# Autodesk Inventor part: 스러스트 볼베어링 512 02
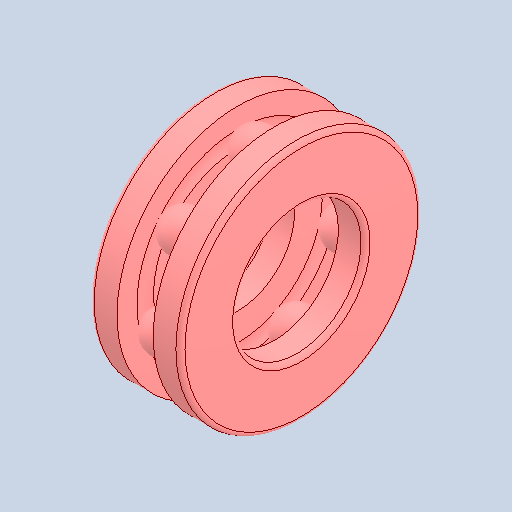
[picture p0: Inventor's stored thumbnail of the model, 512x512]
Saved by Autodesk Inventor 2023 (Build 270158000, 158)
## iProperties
Created: 2024-09
Part Number: 스러스트 볼베어링 512 02
Material: 강철, 연강
Description: 롤링 베어링 - 플랫 뒷면이 있는 스러스트 볼 베어링
Document SubType Name: Modeling
Designer: home
Density: 7.85 g/cm^3
Appearance: 기본값
Author: jhkim
Sending System: Autodesk Inventor 2025
Preprocessor: ST-DEVELOPER v20
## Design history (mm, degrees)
feature "Solid1"
feature "Solid1:1"
feature "Solid1:2"
feature "Solid1:3"
feature "Solid1:4"
feature "Solid1:5"
feature "Solid1:6"
feature "Solid1:7"
feature "Solid1:8"
node "솔리드1"
node "솔리드2"
node "솔리드3"
node "솔리드4"
node "솔리드5"
node "솔리드6"
node "솔리드7"
node "솔리드8"
node "솔리드9"
